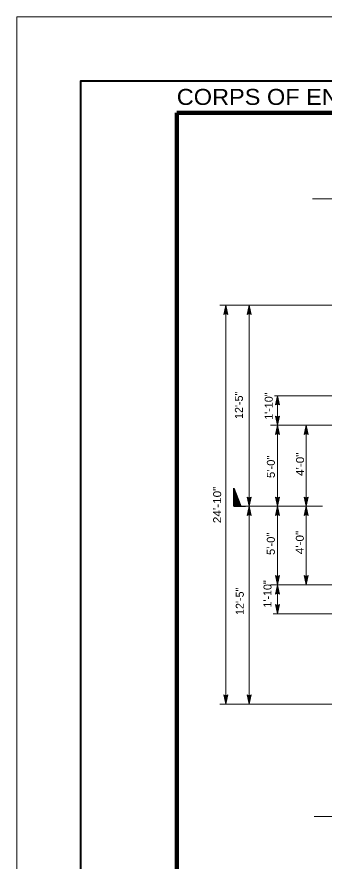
# Model space of a CAD drawing. Extents: x -24.3 to 17.7, y -17.6 to 12.4.
# Drawn here: x -24.34 to -19.54, y -0.8 to 12.39 of the extents above; entities that cross this region are included whole.
import ezdxf
from ezdxf.enums import TextEntityAlignment as Align

# ---------------------------------------------------------------- set-up
doc = ezdxf.new("R2010")
doc.units = 0
doc.header["$LTSCALE"] = 0.05
doc.layers.add('1', color=7, linetype='Continuous', lineweight=13)
doc.layers.add('2', color=7, linetype='Continuous', lineweight=13)

msp = doc.modelspace()

# ---------------------------------------------------------------- linework, layer by layer
at = {"layer": '1'}
for p, q in [((-24.34269, -17.6106), (-24.34269, 12.3894)), ((-19.72169, 9.5474), (-19.16669, 9.5474)), ((-18.50269, 7.8864), (-21.16869, 7.8864)), ((-21.07569, 7.8864), (-21.10669, 7.7424)), ((-21.07569, 7.8494), (-21.09569, 7.7554)), ((-21.07569, 7.8134), (-21.08469, 7.7684)), ((-21.07569, 1.6554), (-21.07569, 7.8864)), ((-21.07569, 7.8864), (-21.04469, 7.7424)), ((-21.07569, 7.8494), (-21.05569, 7.7554)), ((-21.07569, 7.8134), (-21.06569, 7.7684)), ((-20.71169, 7.8864), (-20.74269, 7.7424)), ((-20.71169, 7.8494), (-20.73169, 7.7554)), ((-20.71169, 7.8134), (-20.72069, 7.7684)), ((-20.71169, 7.8864), (-20.68069, 7.7424)), ((-20.71169, 7.8494), (-20.69169, 7.7554)), ((-20.71169, 7.8134), (-20.70169, 7.7684)), ((-21.07569, 7.7644), (-21.09569, 7.7554)), ((-21.07569, 7.7724), (-21.08469, 7.7684)), ((-21.06569, 7.7684), (-21.07569, 7.7724)), ((-21.05569, 7.7554), (-21.07569, 7.7644)), ((-20.71169, 7.7644), (-20.73169, 7.7554)), ((-20.71169, 7.7724), (-20.72069, 7.7684)), ((-20.70169, 7.7684), (-20.71169, 7.7724)), ((-20.69169, 7.7554), (-20.71169, 7.7644)), ((-19.09169, 6.4724), (-20.31569, 6.4724)), ((-20.26769, 6.4724), (-20.29869, 6.3284)), ((-20.26769, 6.4724), (-20.23669, 6.3284)), ((-20.26769, 6.4354), (-20.28769, 6.3414)), ((-20.26769, 6.3504), (-20.28769, 6.3414)), ((-20.26769, 6.3994), (-20.27669, 6.3544)), ((-20.26769, 6.3584), (-20.27669, 6.3544)), ((-20.26769, 6.4354), (-20.24769, 6.3414)), ((-20.26769, 6.3994), (-20.25769, 6.3544)), ((-20.25769, 6.3544), (-20.26769, 6.3584)), ((-20.24769, 6.3414), (-20.26769, 6.3504)), ((-20.26769, 6.0104), (-20.29869, 6.1544)), ((-20.26769, 6.0474), (-20.28769, 6.1414)), ((-20.28769, 6.1414), (-20.26769, 6.1324)), ((-20.26769, 6.0834), (-20.27769, 6.1284)), ((-20.27769, 6.1284), (-20.26769, 6.1244)), ((-20.26769, 6.0104), (-20.23669, 6.1544)), ((-20.26769, 6.0474), (-20.24769, 6.1414)), ((-20.26769, 6.1324), (-20.24769, 6.1414)), ((-20.26769, 6.0834), (-20.25869, 6.1284)), ((-20.26769, 6.1244), (-20.25869, 6.1284)), ((-19.12869, 6.0104), (-20.37669, 6.0104)), ((-20.26769, 6.0104), (-20.29869, 5.8664)), ((-20.26769, 5.9734), (-20.28769, 5.8794)), ((-20.26769, 5.9374), (-20.27669, 5.8924)), ((-20.26769, 6.0104), (-20.23669, 5.8664)), ((-20.26769, 5.9734), (-20.24769, 5.8794)), ((-20.26769, 5.9374), (-20.25769, 5.8924)), ((-19.81769, 6.0104), (-19.84869, 5.8664)), ((-19.81769, 5.9734), (-19.83769, 5.8794)), ((-19.81769, 5.9374), (-19.82669, 5.8924)), ((-19.81769, 6.0104), (-19.78669, 5.8664)), ((-19.81769, 5.9734), (-19.79769, 5.8794)), ((-19.81769, 5.9374), (-19.80769, 5.8924)), ((-20.26769, 5.8884), (-20.28769, 5.8794)), ((-20.26769, 5.8964), (-20.27669, 5.8924)), ((-20.25769, 5.8924), (-20.26769, 5.8964)), ((-20.24769, 5.8794), (-20.26769, 5.8884)), ((-19.81769, 5.8884), (-19.83769, 5.8794)), ((-19.81769, 5.8964), (-19.82669, 5.8924)), ((-19.80769, 5.8924), (-19.81769, 5.8964)), ((-19.79769, 5.8794), (-19.81769, 5.8884)), ((-20.71169, 4.7464), (-20.74269, 4.8904)), ((-20.71169, 4.7464), (-20.68069, 4.8904)), ((-20.26769, 4.7464), (-20.29869, 4.8904)), ((-20.26769, 4.7464), (-20.23669, 4.8904)), ((-19.81769, 4.7464), (-19.84869, 4.8904)), ((-19.81769, 4.7464), (-19.78669, 4.8904)), ((-20.71169, 4.7834), (-20.73169, 4.8774)), ((-20.73169, 4.8774), (-20.71169, 4.8684)), ((-20.71169, 4.8194), (-20.72169, 4.8644)), ((-20.72169, 4.8644), (-20.71169, 4.8604)), ((-20.71169, 4.7834), (-20.69169, 4.8774)), ((-20.71169, 4.8684), (-20.69169, 4.8774)), ((-20.71169, 4.8194), (-20.70269, 4.8644)), ((-20.71169, 4.8604), (-20.70269, 4.8644)), ((-20.26769, 4.7834), (-20.28769, 4.8774)), ((-20.28769, 4.8774), (-20.26769, 4.8684)), ((-20.26769, 4.8194), (-20.27769, 4.8644)), ((-20.27769, 4.8644), (-20.26769, 4.8604)), ((-20.26769, 4.7834), (-20.24769, 4.8774)), ((-20.26769, 4.8684), (-20.24769, 4.8774)), ((-20.26769, 4.8194), (-20.25869, 4.8644)), ((-20.26769, 4.8604), (-20.25869, 4.8644)), ((-19.81769, 4.7834), (-19.83769, 4.8774)), ((-19.83769, 4.8774), (-19.81769, 4.8684)), ((-19.81769, 4.8194), (-19.82769, 4.8644)), ((-19.82769, 4.8644), (-19.81769, 4.8604)), ((-19.81769, 4.7834), (-19.79769, 4.8774)), ((-19.81769, 4.8684), (-19.79769, 4.8774)), ((-19.81769, 4.8194), (-19.80869, 4.8644)), ((-19.81769, 4.8604), (-19.80869, 4.8644)), ((-19.56569, 4.7464), (-20.78269, 4.7464)), ((-20.71169, 4.7464), (-20.74269, 4.6024)), ((-20.71169, 4.7094), (-20.73169, 4.6154)), ((-20.71169, 4.6244), (-20.73169, 4.6154)), ((-20.71169, 4.6734), (-20.72069, 4.6284)), ((-20.71169, 4.6324), (-20.72069, 4.6284)), ((-20.71169, 4.7464), (-20.68069, 4.6024)), ((-20.71169, 4.7094), (-20.69169, 4.6154)), ((-20.71169, 4.6734), (-20.70169, 4.6284)), ((-20.70169, 4.6284), (-20.71169, 4.6324)), ((-20.69169, 4.6154), (-20.71169, 4.6244)), ((-20.26769, 4.7464), (-20.29869, 4.6024)), ((-20.26769, 4.7094), (-20.28769, 4.6154)), ((-20.26769, 4.6244), (-20.28769, 4.6154)), ((-20.26769, 4.6734), (-20.27669, 4.6284)), ((-20.26769, 4.6324), (-20.27669, 4.6284)), ((-20.26769, 4.7464), (-20.23669, 4.6024)), ((-20.26769, 4.7094), (-20.24769, 4.6154)), ((-20.26769, 4.6734), (-20.25769, 4.6284)), ((-20.25769, 4.6284), (-20.26769, 4.6324)), ((-20.24769, 4.6154), (-20.26769, 4.6244)), ((-19.81769, 4.7464), (-19.84869, 4.6024)), ((-19.81769, 4.7094), (-19.83769, 4.6154)), ((-19.81769, 4.6244), (-19.83769, 4.6154)), ((-19.81769, 4.6734), (-19.82669, 4.6284)), ((-19.81769, 4.6324), (-19.82669, 4.6284)), ((-19.81769, 4.7464), (-19.78669, 4.6024)), ((-19.81769, 4.7094), (-19.79769, 4.6154)), ((-19.81769, 4.6734), (-19.80769, 4.6284)), ((-19.80769, 4.6284), (-19.81769, 4.6324)), ((-19.79769, 4.6154), (-19.81769, 4.6244)), ((-20.26769, 3.5184), (-20.29869, 3.6624)), ((-20.26769, 3.5554), (-20.28769, 3.6494)), ((-20.28769, 3.6494), (-20.26769, 3.6404)), ((-20.26769, 3.5914), (-20.27769, 3.6364)), ((-20.27769, 3.6364), (-20.26769, 3.6324)), ((-20.26769, 3.5184), (-20.23669, 3.6624)), ((-20.26769, 3.5554), (-20.24769, 3.6494)), ((-20.26769, 3.6404), (-20.24769, 3.6494)), ((-20.26769, 3.5914), (-20.25869, 3.6364)), ((-20.26769, 3.6324), (-20.25869, 3.6364)), ((-19.81769, 3.5184), (-19.84869, 3.6624)), ((-19.81769, 3.5554), (-19.83769, 3.6494)), ((-19.83769, 3.6494), (-19.81769, 3.6404)), ((-19.81769, 3.5914), (-19.82769, 3.6364)), ((-19.82769, 3.6364), (-19.81769, 3.6324)), ((-19.81769, 3.5184), (-19.78669, 3.6624)), ((-19.81769, 3.5554), (-19.79769, 3.6494)), ((-19.81769, 3.6404), (-19.79769, 3.6494)), ((-19.81769, 3.5914), (-19.80869, 3.6364)), ((-19.81769, 3.6324), (-19.80869, 3.6364)), ((-19.12869, 3.5184), (-20.37669, 3.5184)), ((-20.26769, 3.5184), (-20.29869, 3.3744)), ((-20.26769, 3.4814), (-20.28769, 3.3874)), ((-20.26769, 3.4454), (-20.27669, 3.4004)), ((-20.26769, 3.5184), (-20.23669, 3.3744)), ((-20.26769, 3.4814), (-20.24769, 3.3874)), ((-20.26769, 3.4454), (-20.25769, 3.4004)), ((-20.26769, 3.3964), (-20.28769, 3.3874)), ((-20.26769, 3.4044), (-20.27669, 3.4004)), ((-20.25769, 3.4004), (-20.26769, 3.4044)), ((-20.24769, 3.3874), (-20.26769, 3.3964)), ((-20.26769, 3.0674), (-20.29869, 3.2114)), ((-20.26769, 3.1044), (-20.28769, 3.1984)), ((-20.28769, 3.1984), (-20.26769, 3.1894)), ((-20.26769, 3.1404), (-20.27769, 3.1854)), ((-20.27769, 3.1854), (-20.26769, 3.1814)), ((-20.26769, 3.0674), (-20.23669, 3.2114)), ((-20.26769, 3.1044), (-20.24769, 3.1984)), ((-20.26769, 3.1894), (-20.24769, 3.1984)), ((-20.26769, 3.1404), (-20.25869, 3.1854)), ((-20.26769, 3.1814), (-20.25869, 3.1854)), ((-19.09169, 3.0674), (-20.33369, 3.0674)), ((-21.07569, 1.6554), (-21.10669, 1.7994)), ((-21.07569, 1.6924), (-21.09569, 1.7864)), ((-21.09569, 1.7864), (-21.07569, 1.7774)), ((-21.07569, 1.7284), (-21.08569, 1.7734)), ((-21.08569, 1.7734), (-21.07569, 1.7694)), ((-21.07569, 1.6554), (-21.04469, 1.7994)), ((-21.07569, 1.6924), (-21.05569, 1.7864)), ((-21.07569, 1.7774), (-21.05569, 1.7864)), ((-21.07569, 1.7284), (-21.06669, 1.7734)), ((-21.07569, 1.7694), (-21.06669, 1.7734)), ((-20.71169, 1.6554), (-20.74269, 1.7994)), ((-20.71169, 1.6924), (-20.73169, 1.7864)), ((-20.73169, 1.7864), (-20.71169, 1.7774)), ((-20.71169, 1.7284), (-20.72169, 1.7734)), ((-20.72169, 1.7734), (-20.71169, 1.7694)), ((-20.71169, 1.6554), (-20.68069, 1.7994)), ((-20.71169, 1.6924), (-20.69169, 1.7864)), ((-20.71169, 1.7774), (-20.69169, 1.7864)), ((-20.71169, 1.7284), (-20.70269, 1.7734)), ((-20.71169, 1.7694), (-20.70269, 1.7734)), ((-18.50269, 1.6554), (-21.16869, 1.6554)), ((-19.69369, -0.0986), (-19.13869, -0.0986))]:
    msp.add_line(p, q, dxfattribs=at)
for points in [[(-24.34269, 12.3894), (17.65731, 12.3894), (17.65731, -17.6106)], [(-20.71169, 1.6554), (-20.71169, 4.7464), (-20.71169, 7.8864)], [(-21.04469, 7.7424), (-21.07569, 7.7564), (-21.10669, 7.7424)], [(-20.68069, 7.7424), (-20.71169, 7.7564), (-20.74269, 7.7424)], [(-20.26769, 3.0674), (-20.26769, 3.5184), (-20.26769, 4.7464), (-20.26769, 6.0104), (-20.26769, 6.4724)], [(-20.23669, 6.3284), (-20.26769, 6.3424), (-20.29869, 6.3284)], [(-20.29869, 6.1544), (-20.26769, 6.1404), (-20.23669, 6.1544)], [(-19.81769, 3.5184), (-19.81769, 4.7464), (-19.81769, 6.0104)], [(-20.23669, 5.8664), (-20.26769, 5.8804), (-20.29869, 5.8664)], [(-19.78669, 5.8664), (-19.81769, 5.8804), (-19.84869, 5.8664)], [(-20.74269, 4.8904), (-20.71169, 4.8764), (-20.68069, 4.8904)], [(-20.29869, 4.8904), (-20.26769, 4.8764), (-20.23669, 4.8904)], [(-19.84869, 4.8904), (-19.81769, 4.8764), (-19.78669, 4.8904)], [(-20.68069, 4.6024), (-20.71169, 4.6164), (-20.74269, 4.6024)], [(-20.23669, 4.6024), (-20.26769, 4.6164), (-20.29869, 4.6024)], [(-19.78669, 4.6024), (-19.81769, 4.6164), (-19.84869, 4.6024)], [(-20.29869, 3.6624), (-20.26769, 3.6484), (-20.23669, 3.6624)], [(-19.84869, 3.6624), (-19.81769, 3.6484), (-19.78669, 3.6624)], [(-20.23669, 3.3744), (-20.26769, 3.3884), (-20.29869, 3.3744)], [(-20.29869, 3.2114), (-20.26769, 3.1974), (-20.23669, 3.2114)], [(-21.10669, 1.7994), (-21.07569, 1.7854), (-21.04469, 1.7994)], [(-20.74269, 1.7994), (-20.71169, 1.7854), (-20.68069, 1.7994)]]:
    msp.add_lwpolyline(points, dxfattribs=at)
at = {"layer": '1', "lineweight": 40}
msp.add_lwpolyline([(-23.34269, -16.6106), (-23.34269, 11.3894), (16.65731, 11.3894), (16.65731, -16.6106)], close=True, dxfattribs=at)
at = {"layer": '1', "lineweight": 90}
msp.add_lwpolyline([(-21.84269, 10.8894), (16.15731, 10.8894), (16.15731, -16.1106), (-21.84269, -16.1106)], close=True, dxfattribs=at)
at = {"layer": '2', "lineweight": 25}
for p, q in [((-20.95169, 5.0074), (-20.84869, 4.7464)), ((-20.95169, 4.9824), (-20.85769, 4.7464)), ((-20.95169, 4.9654), (-20.86469, 4.7464)), ((-20.95169, 4.9384), (-20.87569, 4.7464)), ((-20.95169, 4.9124), (-20.88569, 4.7464)), ((-20.95169, 4.8824), (-20.89769, 4.7464)), ((-20.95169, 4.8614), (-20.90569, 4.7464)), ((-20.95169, 4.8374), (-20.91469, 4.7464)), ((-20.95169, 4.8164), (-20.92369, 4.7464)), ((-20.95169, 4.7944), (-20.93269, 4.7464)), ((-20.95169, 4.7794), (-20.93869, 4.7464)), ((-20.95169, 4.7594), (-20.94669, 4.7464)), ((-20.95169, 4.7464), (-20.76569, 4.7464))]:
    msp.add_line(p, q, dxfattribs=at)
msp.add_lwpolyline([(-20.95169, 4.7464), (-20.95169, 5.0304), (-20.83969, 4.7464)], dxfattribs=at)

# ---------------------------------------------------------------- texts
at = {"layer": '1', "width": 1.1}
msp.add_text('CORPS OF ENGINEERS', height=0.25, dxfattribs=at).set_placement((-21.84269, 11.0144))
at = {"layer": '1'}
for s, p in [('12\'-5"', (-20.80869, 6.3224)), ('1\'-10"', (-20.34269, 6.3099)), ('1\'-10"', (-20.36169, 3.3769)), ('12\'-5"', (-20.79469, 3.2614))]:
    msp.add_text(s, height=0.125, rotation=90, dxfattribs=at).set_placement(p, align=Align.CENTER)
for s, width, p in [('4\'-0"', 1.1, (-19.85269, 5.4014)), ('5\'-0"', 1.05, (-20.30869, 5.3624)), ('4\'-0"', 1.1, (-19.85669, 4.1794)), ('5\'-0"', 1.05, (-20.30969, 4.1594))]:
    msp.add_text(s, height=0.125, rotation=90, dxfattribs=dict(at, width=width)).set_placement(p, align=Align.CENTER)
at = {"layer": '1', "width": 1.1}
msp.add_text('24\'-10"', height=0.125, rotation=90, dxfattribs=at).set_placement((-21.14869, 4.4814))

doc.saveas('drawing.dxf')
